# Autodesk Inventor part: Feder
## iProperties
Shininess: 64.0
Length Units: 11269
Angle Units: 11279
Time Units: 11290
Mass Units: 11283
Length Display Precision: 3
Angle Display Precision: 2
Compacted: True
Part Number: Feder
Document SubType Name: Modeling
Created: 2004-08
Material: Standard
Designer: mp
Manufacturer: Standard
Standards Organization: Custom
Density: 0.0
Volumn: 0.0
Area: 0.0
PropertySet Name: Model Information
Control State: 0
Master: False
Checked Out: False
Author: mp
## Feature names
1. Spirale1
2. Sweeping1
3. Sweeping2
